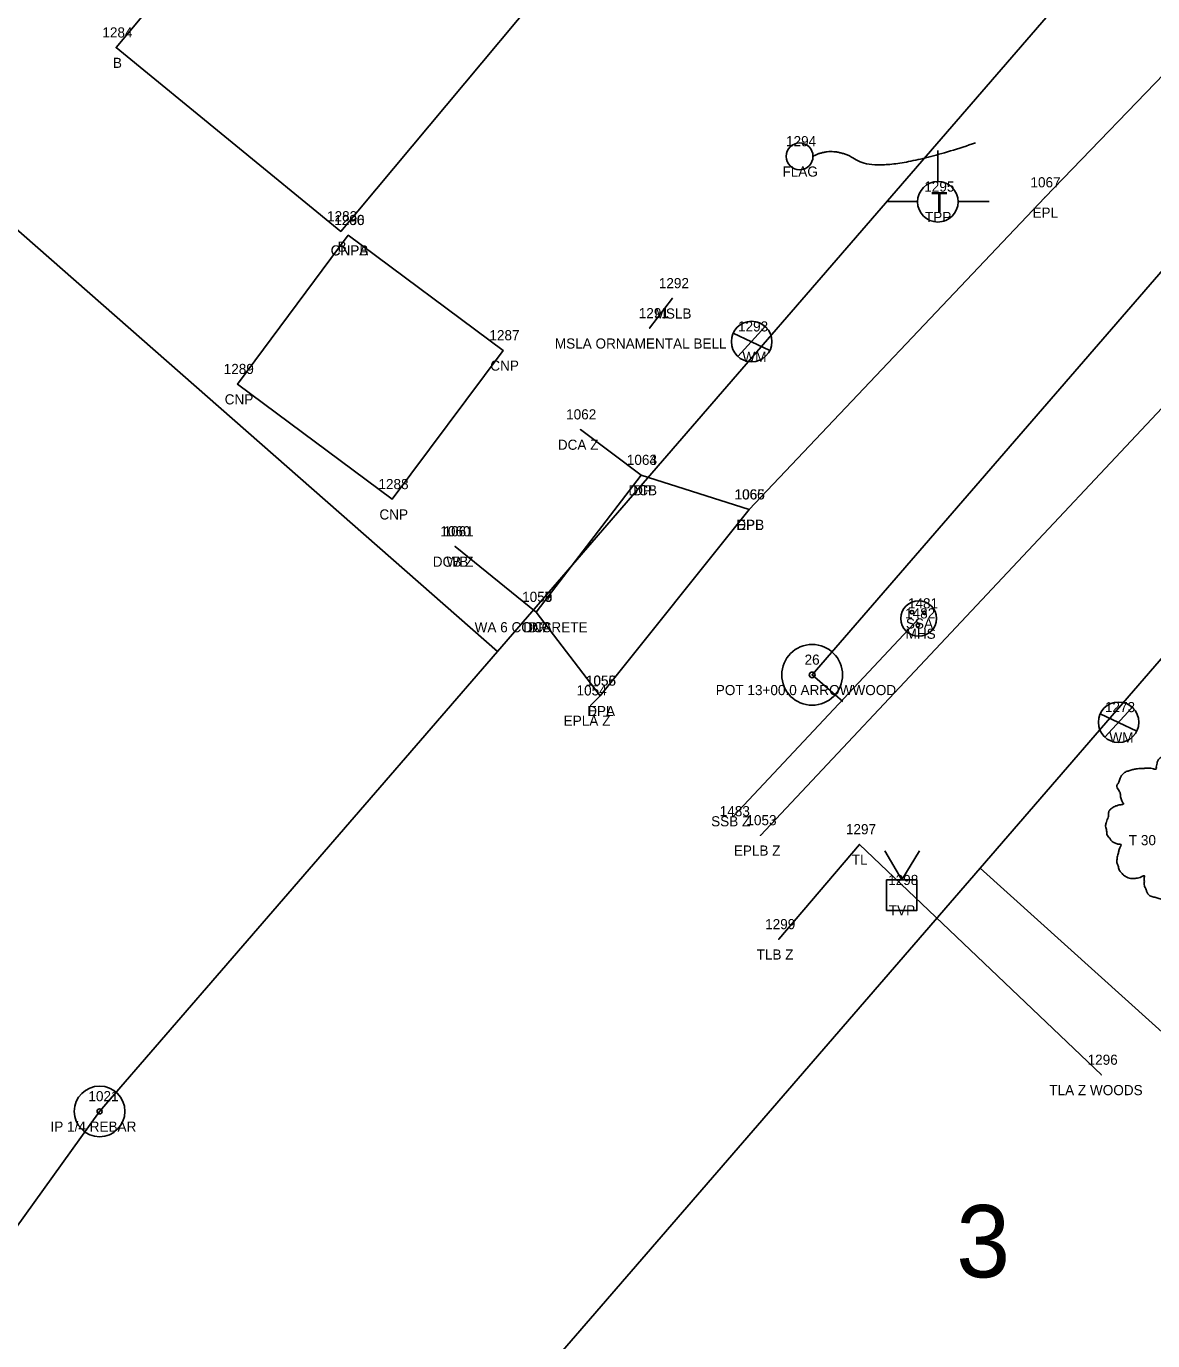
# Model space of a CAD drawing. Extents: x 1812113 to 1819860, y 1177290 to 1181185.
# Drawn here: x 1813774.2 to 1813885.3, y 1178145.9 to 1178275.6 of the extents above; entities that cross this region are included whole.
import ezdxf

# ---------------------------------------------------------------- set-up
doc = ezdxf.new("R2010")
doc.units = 0
for name, color, linetype in [('RD_EX_Bldg', 7, 'Continuous'), ('RD_EX_Bldg_txCode', 7, 'Continuous'), ('RD_EX_BldgApp', 7, 'Continuous'), ('RD_EX_BldgApp_txCode', 7, 'Continuous'), ('RD_EX_Conc', 7, 'Continuous'), ('RD_EX_Conc_txCode', 7, 'Continuous'), ('RD_EX_DR_Inlet', 7, 'Continuous'), ('RD_EX_Driveway', 7, 'Continuous'), ('RD_EX_Driveway_txCode', 7, 'Continuous'), ('RD_EX_DV_Prop', 7, 'Continuous'), ('RD_EX_DV_Prop_txCode', 7, 'Continuous'), ('RD_EX_DV_PropPin', 7, 'Continuous'), ('RD_EX_DV_TX_Prop', 7, 'Continuous'), ('RD_EX_Misc', 7, 'Continuous'), ('RD_EX_Misc_txCode', 7, 'Continuous'), ('RD_EX_Road', 7, 'Continuous'), ('RD_EX_Road_txCode', 7, 'Continuous'), ('RD_EX_SU_Telecom', 7, 'Continuous'), ('RD_EX_UT', 7, 'Continuous'), ('RD_EX_UT_txCode', 7, 'Continuous'), ('RD_EX_VEG', 7, 'Continuous'), ('RD_EX_VEG_txCode', 7, 'Continuous'), ('RD_HC_CL', 7, 'Continuous'), ('RD_HC_Data', 7, 'Continuous'), ('RD_HC_Data_Tic', 7, 'Continuous'), ('RD_HC_txCode', 7, 'Continuous'), ('RD_SMD_Locator', 7, 'Continuous')]:
    doc.layers.add(name, color=color, linetype=linetype)

msp = doc.modelspace()

# ---------------------------------------------------------------- linework, layer by layer
at = {"layer": 'RD_EX_Bldg'}
msp.add_lwpolyline([(1813814.41, 1178311.05), (1813836.59, 1178292.91), (1813805.22, 1178255.39), (1813783.05, 1178273.53), (1813814.41, 1178311.05)], dxfattribs=at)
at = {"layer": 'RD_EX_BldgApp'}
msp.add_line((1813824.51, 1178217.83), (1813816.5, 1178224.3), dxfattribs=at)
msp.add_lwpolyline([(1813805.96, 1178255.02), (1813821.24, 1178243.65), (1813810.29, 1178228.96), (1813795.02, 1178240.32), (1813805.96, 1178255.02)], dxfattribs=at)
at = {"layer": 'RD_EX_Conc'}
for p, q in [((1813828.87, 1178235.84), (1813834.86, 1178231.35)), ((1813824.51, 1178217.83), (1813816.5, 1178224.3))]:
    msp.add_line(p, q, dxfattribs=at)
at = {"layer": 'RD_EX_DR_Inlet'}
for centre, radius in [((1813862.25, 1178217.19), 1.75), ((1813861.59, 1178217.82), 0.175), ((1813862.81, 1178217.75), 0.175), ((1813862.17, 1178216.52), 0.175)]:
    msp.add_circle(centre, radius, dxfattribs=at)
at = {"layer": 'RD_EX_Driveway'}
msp.add_lwpolyline([(1813830.81, 1178209.56), (1813824.51, 1178217.83), (1813834.86, 1178231.35), (1813845.51, 1178227.94)], dxfattribs=at)
at = {"layer": 'RD_EX_DV_Prop'}
for p, q in [((1813820.68, 1178213.93), (1813702.17, 1178317.99)), ((1813820.68, 1178213.93), (1813876.31, 1178278.23)), ((1813868.31, 1178192.56), (1813914.12, 1178245.52)), ((1813781.43, 1178168.55), (1813820.68, 1178213.93)), ((1813819.24, 1178135.84), (1813868.31, 1178192.56)), ((1813868.31, 1178192.56), (1814033.95, 1178043.26)), ((1813768.12, 1178150.07), (1813781.43, 1178168.55))]:
    msp.add_line(p, q, dxfattribs=at)
at = {"layer": 'RD_EX_DV_PropPin'}
for radius in [2.5, 0.25]:
    msp.add_circle((1813781.43, 1178168.55), radius, dxfattribs=at)
at = {"layer": 'RD_EX_Misc'}
msp.add_line((1813835.69, 1178245.83), (1813837.95, 1178248.79), dxfattribs=at)
at = {"layer": 'RD_EX_Road'}
for p, q in [((1813874.69, 1178258.74), (1813910.02, 1178295.38)), ((1813845.51, 1178227.94), (1813874.69, 1178258.74)), ((1813888.9, 1178240.78), (1813846.63, 1178195.79)), ((1813830.81, 1178209.56), (1813845.51, 1178227.94)), ((1813829.87, 1178208.6), (1813830.81, 1178209.56))]:
    msp.add_line(p, q, dxfattribs=at)
at = {"layer": 'RD_EX_SU_Telecom'}
msp.add_circle((1813850.5, 1178262.8), 1.32, dxfattribs=at)
msp.add_open_spline([(1813851.82, 1178262.8), (1813853.83, 1178263.9), (1813858.51, 1178260.95), (1813867.87, 1178264.13)], degree=2, dxfattribs=at)
at = {"layer": 'RD_EX_UT'}
for p, q in [((1813864.14, 1178263.39), (1813864.14, 1178260.32)), ((1813859.21, 1178258.34), (1813862.14, 1178258.34)), ((1813866.14, 1178258.34), (1813869.21, 1178258.34)), ((1813843.94, 1178245.36), (1813847.57, 1178243.65)), ((1813844.42, 1178243.06), (1813847.08, 1178245.96)), ((1813862.26, 1178217.2), (1813843.97, 1178197.68)), ((1813880.15, 1178207.79), (1813883.78, 1178206.07)), ((1813880.63, 1178205.49), (1813883.29, 1178208.39)), ((1813860.58, 1178191.39), (1813858.92, 1178194.28)), ((1813860.58, 1178191.39), (1813862.32, 1178194.28))]:
    msp.add_line(p, q, dxfattribs=at)
msp.add_lwpolyline([(1813859.08, 1178188.39), (1813859.08, 1178191.39), (1813862.08, 1178191.39), (1813862.08, 1178188.39)], close=True, dxfattribs=at)
for centre in [(1813864.14, 1178258.32), (1813845.77, 1178244.52), (1813881.98, 1178206.95)]:
    msp.add_circle(centre, 2, dxfattribs=at)
at = {"layer": 'RD_EX_VEG'}
msp.add_lwpolyline([(1813880.29, 1178172.15), (1813856.42, 1178194.9), (1813848.45, 1178185.53)], dxfattribs=at)
msp.add_spline([(1813887.77, 1178203.99), (1813887.47, 1178204.02), (1813887.15, 1178203.92), (1813886.9, 1178203.82), (1813886.67, 1178203.74), (1813886.45, 1178203.64), (1813886.15, 1178203.47), (1813885.92, 1178203.27), (1813885.8, 1178203.02), (1813885.75, 1178202.79), (1813885.7, 1178202.52), (1813885.7, 1178202.34), (1813885.57, 1178202.32), (1813885.42, 1178202.34), (1813885.17, 1178202.42), (1813884.92, 1178202.42), (1813884.67, 1178202.42), (1813884.32, 1178202.39), (1813883.97, 1178202.39), (1813883.7, 1178202.34), (1813883.37, 1178202.29), (1813883, 1178202.17), (1813882.65, 1178202.04), (1813882.35, 1178201.79), (1813882.1, 1178201.32), (1813881.97, 1178200.97), (1813881.82, 1178200.72), (1813881.97, 1178200.27), (1813882.15, 1178199.92), (1813882.17, 1178199.72), (1813882.25, 1178199.29), (1813882.35, 1178199.07), (1813882.47, 1178198.87), (1813882.4, 1178198.84), (1813882.02, 1178198.79), (1813881.72, 1178198.69), (1813881.3, 1178198.47), (1813881.07, 1178198.24), (1813880.97, 1178197.92), (1813880.95, 1178197.57), (1813880.85, 1178197.37), (1813880.77, 1178197.09), (1813880.75, 1178197.02), (1813880.7, 1178196.69), (1813880.8, 1178196.24), (1813880.82, 1178195.89), (1813880.95, 1178195.67), (1813881.1, 1178195.5), (1813881.27, 1178195.25), (1813881.67, 1178195.02), (1813882, 1178194.92), (1813882.2, 1178194.9), (1813882.02, 1178194.4), (1813881.97, 1178194.05), (1813881.85, 1178193.65), (1813881.85, 1178193.57), (1813881.8, 1178193.1), (1813881.95, 1178192.77), (1813882.02, 1178192.4), (1813882.2, 1178192.17), (1813882.47, 1178191.87), (1813882.8, 1178191.65), (1813883.3, 1178191.52), (1813883.7, 1178191.55), (1813884.27, 1178191.72), (1813884.52, 1178191.8), (1813884.5, 1178191.62), (1813884.52, 1178191.25), (1813884.52, 1178190.82), (1813884.67, 1178190.5), (1813884.77, 1178190.22), (1813884.92, 1178189.97), (1813885.25, 1178189.75), (1813885.65, 1178189.67), (1813886.07, 1178189.52), (1813886.52, 1178189.45), (1813887.02, 1178189.42), (1813887.62, 1178189.57), (1813887.9, 1178189.7), (1813888, 1178189.87), (1813888.2, 1178190.25), (1813888.15, 1178190.47), (1813888.17, 1178191.07), (1813888.27, 1178190.9), (1813888.45, 1178190.55), (1813888.95, 1178190.25), (1813889.34, 1178190.07), (1813889.82, 1178189.92), (1813890.12, 1178189.85), (1813890.59, 1178189.92), (1813890.97, 1178190), (1813891.34, 1178190.12), (1813891.64, 1178190.4), (1813891.82, 1178190.67), (1813891.87, 1178190.95), (1813891.94, 1178191.32), (1813891.99, 1178191.5)], degree=3, dxfattribs=at)
at = {"layer": 'RD_HC_CL'}
msp.add_line((1814048.02, 1178438.51), (1813851.74, 1178211.63), dxfattribs=at)
at = {"layer": 'RD_HC_Data'}
for radius in [3, 0.282]:
    msp.add_circle((1813851.74, 1178211.63), radius, dxfattribs=at)
at = {"layer": 'RD_HC_Data_Tic'}
msp.add_line((1813851.74, 1178211.63), (1813854.77, 1178209.01), dxfattribs=at)
at = {"layer": 'RD_SMD_Locator'}
for centre in [(1813783.05, 1178273.53), (1813874.69, 1178258.74), (1813805.22, 1178255.39), (1813805.96, 1178255.02), (1813805.96, 1178255.02), (1813837.95, 1178248.79), (1813835.69, 1178245.83), (1813821.24, 1178243.65), (1813795.02, 1178240.32), (1813828.87, 1178235.84), (1813834.86, 1178231.35), (1813834.86, 1178231.35), (1813810.29, 1178228.96), (1813845.51, 1178227.94), (1813845.51, 1178227.94), (1813816.5, 1178224.3), (1813816.5, 1178224.3), (1813824.51, 1178217.83), (1813824.51, 1178217.83), (1813824.51, 1178217.83), (1813862.26, 1178217.2), (1813851.74, 1178211.63), (1813829.87, 1178208.6), (1813830.81, 1178209.56), (1813830.81, 1178209.56), (1813843.97, 1178197.68), (1813846.63, 1178195.79), (1813856.42, 1178194.9), (1813848.45, 1178185.53), (1813880.29, 1178172.15)]:
    msp.add_circle(centre, 0.001, dxfattribs=at)

# ---------------------------------------------------------------- texts
at = {"layer": 'RD_EX_Bldg_txCode'}
for s, p in [('1284', (1813781.7, 1178274.53)), ('B', (1813782.74, 1178271.53)), ('1283', (1813803.87, 1178256.39)), ('B', (1813804.91, 1178253.39))]:
    msp.add_text(s, height=1, dxfattribs=at).set_placement(p)
at = {"layer": 'RD_EX_BldgApp_txCode'}
for s, p in [('1294', (1813849.16, 1178263.8)), ('FLAG', (1813848.81, 1178260.8)), ('1290', (1813804.58, 1178256.02)), ('1286', (1813804.59, 1178256.02)), ('CNPA', (1813804.22, 1178253.02)), ('CNPB', (1813804.24, 1178253.02)), ('1287', (1813819.89, 1178244.65)), ('1289', (1813793.67, 1178241.32)), ('CNP', (1813819.98, 1178241.65)), ('CNP', (1813793.77, 1178238.32)), ('1288', (1813808.94, 1178229.96)), ('CNP', (1813809.04, 1178226.96)), ('1060', (1813815.05, 1178225.3)), ('WB', (1813815.65, 1178222.3)), ('1059', (1813823.12, 1178218.83)), ('WA 6 CONCRETE', (1813818.43, 1178215.83))]:
    msp.add_text(s, height=1, dxfattribs=at).set_placement(p)
at = {"layer": 'RD_EX_Conc_txCode'}
for s, p in [('1062', (1813827.46, 1178236.84)), ('DCA Z', (1813826.64, 1178233.84)), ('1063', (1813833.45, 1178232.35)), ('DCB', (1813833.61, 1178229.35)), ('1061', (1813815.37, 1178225.3)), ('DCB Z', (1813814.3, 1178222.3)), ('1058', (1813823.12, 1178218.83)), ('DCA', (1813823.24, 1178215.83))]:
    msp.add_text(s, height=1, dxfattribs=at).set_placement(p)
at = {"layer": 'RD_EX_Driveway_txCode'}
for s, p in [('1064', (1813833.45, 1178232.35)), ('DP', (1813834.08, 1178229.35)), ('1065', (1813844.1, 1178228.94)), ('DPB', (1813844.26, 1178225.94)), ('1057', (1813823.12, 1178218.83)), ('DP', (1813823.73, 1178215.83)), ('1056', (1813829.4, 1178210.56)), ('DPA', (1813829.54, 1178207.56))]:
    msp.add_text(s, height=1, dxfattribs=at).set_placement(p)
at = {"layer": 'RD_EX_DV_Prop_txCode'}
for s, p in [('1021', (1813780.32, 1178169.55)), ('IP 1/4 REBAR', (1813776.58, 1178166.55))]:
    msp.add_text(s, height=1, dxfattribs=at).set_placement(p)
at = {"layer": 'RD_EX_DV_TX_Prop'}
msp.add_text('3', height=7.14, dxfattribs=at).set_placement((1813865.96, 1178152.17))
at = {"layer": 'RD_EX_Misc_txCode'}
for s, p in [('1292', (1813836.61, 1178249.79)), ('1291', (1813834.63, 1178246.83)), ('MSLB', (1813836.19, 1178246.79)), ('MSLA ORNAMENTAL BELL', (1813826.35, 1178243.83))]:
    msp.add_text(s, height=1, dxfattribs=at).set_placement(p)
at = {"layer": 'RD_EX_Road_txCode'}
for s, p in [('1067', (1813873.28, 1178259.74)), ('EPL', (1813873.48, 1178256.74)), ('1066', (1813844.07, 1178228.94)), ('EPL', (1813844.3, 1178225.94)), ('1055', (1813829.42, 1178210.56)), ('1054', (1813828.49, 1178209.6)), ('EPL', (1813829.6, 1178207.56)), ('EPLA Z', (1813827.22, 1178206.6)), ('1053', (1813845.25, 1178196.79)), ('EPLB Z', (1813844.01, 1178193.79))]:
    msp.add_text(s, height=1, dxfattribs=at).set_placement(p)
at = {"layer": 'RD_EX_UT'}
msp.add_text('T', height=2, dxfattribs=at).set_placement((1813863.47, 1178257.27))
at = {"layer": 'RD_EX_UT_txCode'}
for s, p in [('1295', (1813862.8, 1178259.32)), ('TPP', (1813862.87, 1178256.32)), ('1293', (1813844.42, 1178245.52)), ('WM', (1813844.86, 1178242.52)), ('1481', (1813861.19, 1178218.19)), ('1482', (1813860.91, 1178217.2)), ('SSA', (1813860.99, 1178216.2)), ('MHS', (1813860.96, 1178215.19)), ('1273', (1813880.63, 1178207.95)), ('WM', (1813881.07, 1178204.95)), ('1483', (1813842.62, 1178197.68)), ('SSB Z', (1813841.77, 1178196.68)), ('1298', (1813859.24, 1178190.89)), ('TVP', (1813859.3, 1178187.89))]:
    msp.add_text(s, height=1, dxfattribs=at).set_placement(p)
at = {"layer": 'RD_EX_VEG_txCode'}
for s, p in [('1297', (1813855.07, 1178195.9)), ('T 30 MAPLE', (1813882.99, 1178194.82)), ('TL', (1813855.65, 1178192.9)), ('1299', (1813847.1, 1178186.53)), ('TLB Z', (1813846.26, 1178183.53)), ('1296', (1813878.92, 1178173.15)), ('TLA Z WOODS', (1813875.14, 1178170.15))]:
    msp.add_text(s, height=1, dxfattribs=at).set_placement(p)
at = {"layer": 'RD_HC_txCode'}
for s, p in [('26', (1813850.99, 1178212.63)), ('POT 13+00.0 ARROWWOOD', (1813842.23, 1178209.63))]:
    msp.add_text(s, height=1, dxfattribs=at).set_placement(p)

doc.saveas('drawing.dxf')
